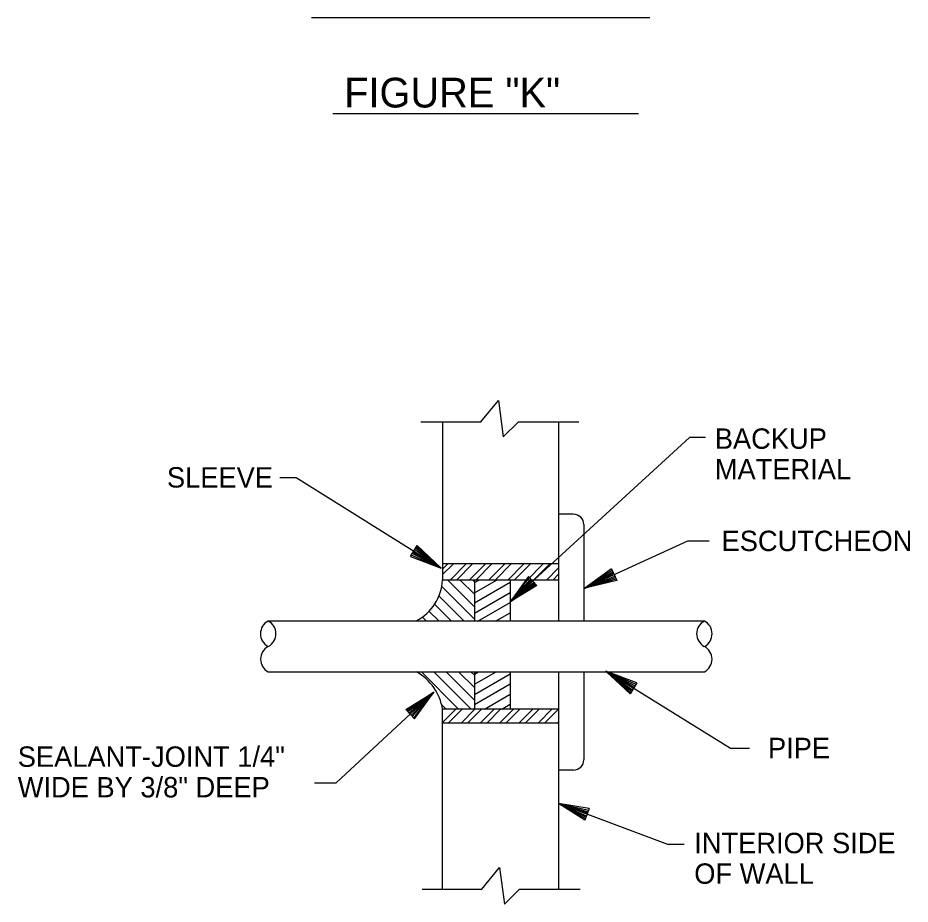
# Model space of a CAD drawing. Extents: x 10040.55 to 10045.84, y 10033.26 to 10035.76.
# Drawn here: x 10041.7142 to 10042.152, y 10034.8637 to 10035.2985 of the extents above; entities that cross this region are included whole.
import ezdxf

# ---------------------------------------------------------------- set-up
doc = ezdxf.new("R2010")
doc.units = 0
doc.layers.add('Level 2', color=7, linetype='Continuous')

msp = doc.modelspace()

# ---------------------------------------------------------------- linework, layer by layer
at = {"layer": 'Level 2'}
for p, q in [((10042.024229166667, 10035.298510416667), (10041.858260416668, 10035.298510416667)), ((10041.868760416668, 10035.251510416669), (10042.018687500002, 10035.251510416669)), ((10041.922635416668, 10035.100343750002), (10041.922635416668, 10035.022729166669)), ((10041.979479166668, 10035.100343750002), (10041.979479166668, 10035.002593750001)), ((10041.98684375, 10035.054979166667), (10041.979479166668, 10035.054979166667)), ((10041.991906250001, 10035.049916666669), (10041.991906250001, 10035.002697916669)), ((10041.906822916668, 10035.034260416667), (10041.910208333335, 10035.039645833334)), ((10041.92196875, 10035.028510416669), (10041.908093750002, 10035.036302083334)), ((10041.908479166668, 10035.036937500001), (10041.92196875, 10035.028510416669)), ((10041.92196875, 10035.028510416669), (10041.908916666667, 10035.037604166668)), ((10041.92196875, 10035.028510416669), (10041.909322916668, 10035.038281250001)), ((10041.92196875, 10035.028510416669), (10041.909739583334, 10035.038916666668)), ((10041.910208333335, 10035.039645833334), (10041.92196875, 10035.028510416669)), ((10041.906822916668, 10035.034260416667), (10041.92196875, 10035.028510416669)), ((10041.92196875, 10035.028510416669), (10041.907250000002, 10035.034947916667)), ((10041.92196875, 10035.028510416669), (10041.907697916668, 10035.035708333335)), ((10041.922562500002, 10035.028020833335), (10041.925197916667, 10035.03065625)), ((10041.979479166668, 10035.030635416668), (10041.922583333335, 10035.030635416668)), ((10041.922614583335, 10035.025385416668), (10041.927885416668, 10035.030635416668)), ((10041.926270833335, 10035.022729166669), (10041.934177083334, 10035.030635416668)), ((10041.929416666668, 10035.022729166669), (10041.937333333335, 10035.030635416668)), ((10041.93571875, 10035.022729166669), (10041.943625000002, 10035.030635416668)), ((10041.938875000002, 10035.022729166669), (10041.94678125, 10035.030635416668)), ((10041.945166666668, 10035.022729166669), (10041.953072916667, 10035.030635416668)), ((10041.948333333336, 10035.022729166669), (10041.956229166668, 10035.030635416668)), ((10041.954625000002, 10035.022729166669), (10041.962520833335, 10035.030635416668)), ((10041.957781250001, 10035.022729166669), (10041.965687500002, 10035.030635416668)), ((10041.964072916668, 10035.022729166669), (10041.971979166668, 10035.030635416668)), ((10041.967229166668, 10035.022729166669), (10041.975135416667, 10035.030635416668)), ((10041.973520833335, 10035.022729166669), (10041.979479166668, 10035.028687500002)), ((10042.005437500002, 10035.028250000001), (10041.992302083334, 10035.018770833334)), ((10041.992302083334, 10035.018770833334), (10042.005770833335, 10035.027520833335)), ((10042.005437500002, 10035.028250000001), (10042.008072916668, 10035.022468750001)), ((10041.964760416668, 10035.024479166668), (10041.955687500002, 10035.012093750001)), ((10041.955687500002, 10035.012093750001), (10041.96528125, 10035.023916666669)), ((10041.955687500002, 10035.012093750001), (10041.965864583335, 10035.023302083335)), ((10041.955687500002, 10035.012093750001), (10041.966302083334, 10035.022802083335)), ((10041.964760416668, 10035.024479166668), (10041.968822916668, 10035.020031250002)), ((10041.976677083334, 10035.022729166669), (10041.979479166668, 10035.025531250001)), ((10041.992302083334, 10035.018770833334), (10042.006166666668, 10035.026718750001)), ((10041.992302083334, 10035.018770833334), (10042.006437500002, 10035.026062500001)), ((10042.006760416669, 10035.025395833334), (10041.992302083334, 10035.018770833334)), ((10041.992302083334, 10035.018770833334), (10042.007072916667, 10035.024666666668)), ((10041.992302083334, 10035.018770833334), (10042.007416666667, 10035.023958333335)), ((10041.992302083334, 10035.018770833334), (10042.007718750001, 10035.023260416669)), ((10041.938218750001, 10035.003520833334), (10041.922104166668, 10035.019635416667)), ((10041.979479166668, 10035.022729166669), (10041.922583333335, 10035.022729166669)), ((10041.938218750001, 10035.009625), (10041.925114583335, 10035.022729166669)), ((10041.938218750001, 10035.015739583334), (10041.931250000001, 10035.022708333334)), ((10041.938218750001, 10035.021854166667), (10041.937364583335, 10035.022697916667)), ((10041.938218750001, 10035.022697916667), (10041.938218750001, 10035.002458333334)), ((10041.938218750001, 10035.016447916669), (10041.949041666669, 10035.022697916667)), ((10041.938218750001, 10035.021437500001), (10041.940395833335, 10035.022697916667)), ((10041.938218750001, 10035.011458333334), (10041.95578125, 10035.021604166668)), ((10041.966781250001, 10035.022291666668), (10041.955687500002, 10035.012093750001)), ((10041.955687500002, 10035.012093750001), (10041.967281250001, 10035.021718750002)), ((10041.955687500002, 10035.012093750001), (10041.967791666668, 10035.021177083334)), ((10041.955687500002, 10035.012093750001), (10041.968281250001, 10035.020635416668)), ((10041.968822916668, 10035.020031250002), (10041.955687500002, 10035.012093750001)), ((10041.95578125, 10035.022697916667), (10041.95578125, 10035.002458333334)), ((10042.008072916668, 10035.022468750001), (10041.992302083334, 10035.018770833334)), ((10041.933125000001, 10035.002520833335), (10041.920697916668, 10035.014927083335)), ((10041.938218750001, 10035.006479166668), (10041.95578125, 10035.016604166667)), ((10041.926958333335, 10035.002572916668), (10041.91859375, 10035.010937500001)), ((10041.939906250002, 10035.002458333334), (10041.95578125, 10035.011635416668)), ((10041.92078125, 10035.002635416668), (10041.915885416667, 10035.007520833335)), ((10041.948552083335, 10035.002458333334), (10041.95578125, 10035.006645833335)), ((10042.051031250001, 10035.002593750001), (10041.837031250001, 10035.002593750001)), ((10041.914614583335, 10035.002687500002), (10041.912625, 10035.004666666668)), ((10041.837031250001, 10034.977677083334), (10042.051031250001, 10034.977677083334)), ((10041.930406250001, 10034.959406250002), (10041.912187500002, 10034.977625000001)), ((10041.936447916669, 10034.959468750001), (10041.918270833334, 10034.977645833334)), ((10041.938218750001, 10034.963812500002), (10041.924354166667, 10034.977666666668)), ((10041.938218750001, 10034.969916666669), (10041.930447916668, 10034.977697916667)), ((10041.938218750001, 10034.976020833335), (10041.936531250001, 10034.977708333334)), ((10041.938218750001, 10034.977708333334), (10041.938218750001, 10034.959489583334)), ((10041.938218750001, 10034.971552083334), (10041.948885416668, 10034.977708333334)), ((10041.938218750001, 10034.976552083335), (10041.940239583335, 10034.977708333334)), ((10041.938218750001, 10034.966572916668), (10041.95578125, 10034.976708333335)), ((10041.95578125, 10034.977708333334), (10041.95578125, 10034.959322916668)), ((10041.979479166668, 10034.977677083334), (10041.979479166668, 10034.871114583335)), ((10041.991906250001, 10034.977791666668), (10041.991906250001, 10034.934541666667)), ((10042.016260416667, 10034.969572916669), (10042.002729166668, 10034.977927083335)), ((10042.014541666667, 10034.966854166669), (10042.002729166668, 10034.977927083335)), ((10042.017906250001, 10034.97225), (10042.002729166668, 10034.977927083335)), ((10042.002729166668, 10034.977927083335), (10042.015427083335, 10034.968218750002)), ((10042.002729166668, 10034.977927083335), (10042.017031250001, 10034.970791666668)), ((10042.002729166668, 10034.977927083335), (10042.015010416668, 10034.967583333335)), ((10042.002729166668, 10034.977927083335), (10042.015822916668, 10034.968895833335)), ((10042.002729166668, 10034.977927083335), (10042.016635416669, 10034.970208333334)), ((10042.002729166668, 10034.977927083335), (10042.017479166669, 10034.9715625)), ((10041.938218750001, 10034.961583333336), (10041.95578125, 10034.971718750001)), ((10042.017906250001, 10034.97225), (10042.014541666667, 10034.966854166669)), ((10041.904510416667, 10034.959218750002), (10041.918312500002, 10034.967697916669)), ((10041.918312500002, 10034.967697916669), (10041.905093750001, 10034.958572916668)), ((10041.918312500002, 10034.967697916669), (10041.905604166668, 10034.958010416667)), ((10041.918312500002, 10034.967697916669), (10041.906145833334, 10034.957437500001)), ((10041.9066875, 10034.956854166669), (10041.918312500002, 10034.967697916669)), ((10041.918312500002, 10034.967697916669), (10041.907197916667, 10034.9563125)), ((10041.918312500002, 10034.967697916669), (10041.907666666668, 10034.95578125)), ((10041.918312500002, 10034.967697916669), (10041.908281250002, 10034.955145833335)), ((10041.908833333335, 10034.954552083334), (10041.918312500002, 10034.967697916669)), ((10041.943145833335, 10034.959437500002), (10041.95578125, 10034.966729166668)), ((10041.924354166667, 10034.959333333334), (10041.922, 10034.961687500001)), ((10041.951635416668, 10034.959354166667), (10041.95578125, 10034.96175)), ((10041.908833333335, 10034.954552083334), (10041.904510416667, 10034.959218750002)), ((10041.979479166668, 10034.959322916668), (10041.922583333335, 10034.959322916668)), ((10041.922583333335, 10034.952885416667), (10041.929020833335, 10034.959322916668)), ((10041.922635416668, 10034.871114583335), (10041.922635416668, 10034.959322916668)), ((10041.922635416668, 10034.959229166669), (10041.922718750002, 10034.959322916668)), ((10041.925500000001, 10034.952656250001), (10041.932166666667, 10034.959322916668)), ((10041.931802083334, 10034.952656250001), (10041.93846875, 10034.959322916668)), ((10041.934947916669, 10034.952656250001), (10041.941614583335, 10034.959322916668)), ((10041.941250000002, 10034.952656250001), (10041.947916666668, 10034.959322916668)), ((10041.94440625, 10034.952656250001), (10041.951072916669, 10034.959322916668)), ((10041.950697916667, 10034.952656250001), (10041.957364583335, 10034.959322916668)), ((10041.953854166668, 10034.952656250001), (10041.960520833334, 10034.959322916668)), ((10041.960156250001, 10034.952656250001), (10041.966822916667, 10034.959322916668)), ((10041.963302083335, 10034.952656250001), (10041.969968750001, 10034.959322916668)), ((10041.969604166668, 10034.952656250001), (10041.976270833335, 10034.959322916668)), ((10041.97275, 10034.952656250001), (10041.979416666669, 10034.959322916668)), ((10041.979052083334, 10034.952656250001), (10041.979479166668, 10034.953072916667)), ((10041.922583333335, 10034.952656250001), (10041.979479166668, 10034.952656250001)), ((10041.98684375, 10034.929479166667), (10041.979479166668, 10034.929479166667)), ((10041.993531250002, 10034.907791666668), (10041.97940625, 10034.913031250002)), ((10041.992447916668, 10034.904947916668), (10041.97940625, 10034.913031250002)), ((10041.994562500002, 10034.910583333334), (10041.97940625, 10034.913031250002)), ((10041.97940625, 10034.913031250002), (10041.993010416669, 10034.906385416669)), ((10041.97940625, 10034.913031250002), (10041.994020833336, 10034.909072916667)), ((10041.97940625, 10034.913031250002), (10041.992739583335, 10034.905708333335)), ((10041.97940625, 10034.913031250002), (10041.993260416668, 10034.907083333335)), ((10041.97940625, 10034.913031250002), (10041.993770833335, 10034.908447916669)), ((10041.97940625, 10034.913031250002), (10041.994291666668, 10034.909864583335)), ((10041.994562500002, 10034.910583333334), (10041.992447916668, 10034.904947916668))]:
    msp.add_line(p, q, dxfattribs=at)
for points in [[(10041.911979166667, 10035.100343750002), (10041.941281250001, 10035.100343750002), (10041.950020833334, 10035.110854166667), (10041.952375, 10035.092937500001), (10041.959802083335, 10035.100343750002), (10041.989510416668, 10035.100343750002)], [(10042.05159375, 10035.092718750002), (10042.043687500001, 10035.092718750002), (10041.955687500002, 10035.012093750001)], [(10041.842833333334, 10035.073072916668), (10041.8508125, 10035.073072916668), (10041.92196875, 10035.028510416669)], [(10042.053354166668, 10035.041802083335), (10042.04271875, 10035.041802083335), (10041.992302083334, 10035.018770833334)], [(10042.073218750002, 10034.940020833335), (10042.063906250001, 10034.940020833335), (10042.002729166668, 10034.977927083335)], [(10041.859791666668, 10034.923145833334), (10041.870427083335, 10034.923145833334), (10041.918312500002, 10034.967697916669)], [(10042.041052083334, 10034.893000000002), (10042.033156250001, 10034.893000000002), (10041.97940625, 10034.913031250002)], [(10041.912500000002, 10034.871114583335), (10041.941802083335, 10034.871114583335), (10041.950541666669, 10034.881625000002), (10041.952895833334, 10034.863708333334), (10041.960322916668, 10034.871114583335), (10041.990031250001, 10034.871114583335)]]:
    msp.add_lwpolyline(points, dxfattribs=at)
for centre, radius, start, end in [((10041.986842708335, 10035.049916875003), 0.005062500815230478, 0, 90), ((10041.89863137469, 10035.024002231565), 0.02398249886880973, 297.50966666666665, 356.963775), ((10041.840264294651, 10034.996356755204), 0.007020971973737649, 117.38482499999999, 241.91503055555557), ((10041.83380549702, 10034.996356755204), 0.007020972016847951, 298.0849694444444, 62.615175), ((10042.05426460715, 10034.996356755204), 0.007020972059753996, 117.38482499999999, 241.91503055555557), ((10042.047805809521, 10034.996356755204), 0.007020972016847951, 298.0849694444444, 62.615175), ((10041.840336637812, 10034.983906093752), 0.0070518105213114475, 117.91829444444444, 242.08170833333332), ((10042.047733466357, 10034.983906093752), 0.007051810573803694, 297.9182916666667, 62.08170555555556), ((10041.897374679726, 10034.955373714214), 0.025513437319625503, 8.91205, 60.69234722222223), ((10041.986842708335, 10034.934542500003), 0.005062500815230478, 270, 0)]:
    msp.add_arc(centre, radius, start, end, dxfattribs=at)

# ---------------------------------------------------------------- texts
for s, height, p in [('FIGURE "K"', 0.014583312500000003, (10041.874333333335, 10035.254541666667)), ('BACKUP', 0.010000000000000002, (10042.056145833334, 10035.087093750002)), ('MATERIAL', 0.010000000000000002, (10042.056145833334, 10035.072093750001)), ('SLEEVE', 0.010000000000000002, (10041.787364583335, 10035.068083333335)), ('ESCUTCHEON', 0.010000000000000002, (10042.059458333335, 10035.036916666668)), ('PIPE', 0.010000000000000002, (10042.082239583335, 10034.935312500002)), ('SEALANT-JOINT 1/4"', 0.010000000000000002, (10041.714166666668, 10034.931083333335)), ('WIDE BY 3/8" DEEP', 0.010000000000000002, (10041.714166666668, 10034.916083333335)), ('INTERIOR SIDE', 0.010000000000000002, (10042.046052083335, 10034.888697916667)), ('OF WALL', 0.010000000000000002, (10042.046052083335, 10034.873697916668))]:
    msp.add_text(s, height=height, dxfattribs=at).set_placement(p)

doc.saveas('drawing.dxf')
